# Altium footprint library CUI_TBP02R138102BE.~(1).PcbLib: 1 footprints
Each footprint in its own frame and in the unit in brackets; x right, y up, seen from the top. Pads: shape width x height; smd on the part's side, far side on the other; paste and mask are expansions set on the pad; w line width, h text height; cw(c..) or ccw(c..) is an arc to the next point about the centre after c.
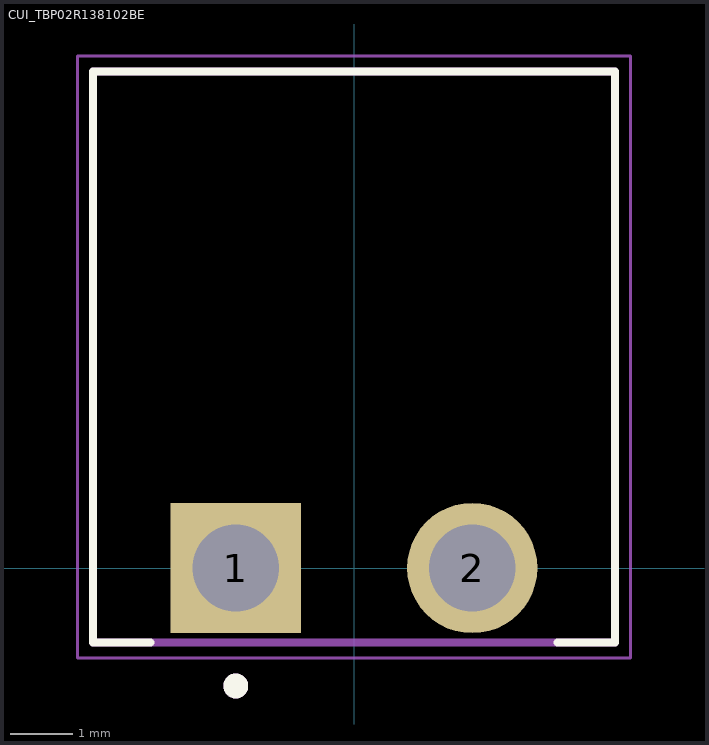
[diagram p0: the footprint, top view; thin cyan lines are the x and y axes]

## CUI_TBP02R138102BE [mm]
height 7.2
pads (2):
  rect 2.1x2.1 / inner round 2.1 / far side rect 2.1x2.1 hole 1.4: 1(-1.905,0)
  round 2.1 hole 1.4: 2(1.905,0)
Top Overlay:
  circle w0.2: c-1.905,-1.9 r0.1
  lines w0.127: -3.275,-1.2 -4.205,-1.2 -4.205,8 4.205,8 4.205,-1.2 3.275,-1.2
Assembly Top:
  circle w0.2: c-1.905,-1.9 r0.1
  lines w0.127: -4.205,-1.2 4.205,-1.2 4.205,8 -4.205,8 -4.205,-1.2
Courtyard Top:
  lines w0.05: -4.455,-1.45 4.455,-1.45 4.455,8.25 -4.455,8.25 -4.455,-1.45
3D body "step_temp.STEP": height 18.2, standoff 9, extent 0,-21.35 10.7,-12.94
